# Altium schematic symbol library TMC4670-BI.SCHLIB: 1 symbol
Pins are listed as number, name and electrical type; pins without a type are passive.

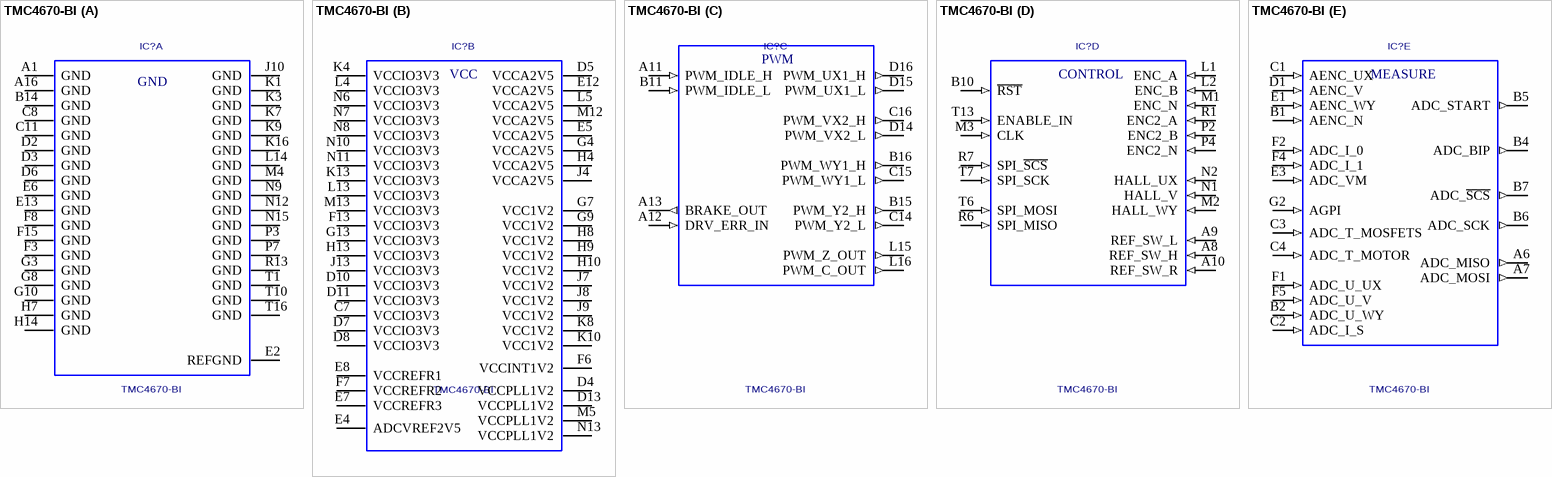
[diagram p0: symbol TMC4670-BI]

## TMC4670-BI
designator IC?
Field oriented servocontrolerfor torque control,velocity control,and positioning. Encoder Engine, PWM-Engine und SPI. BGA256(17x17); Manufacturer: TRINAMIC; Geometry.Height: 2.2mm; PCB DECAL: TMC_BGA256_1.0_17X17
footprint TMC_BGA256_1.0_17X17
part A pins: A1 GND (power), A16 GND (power), B14 GND (power), C8 GND (power), C11 GND (power), D2 GND (power), D3 GND (power), D6 GND (power), E2 REFGND (power), E6 GND (power), E13 GND (power), F3 GND (power), F8 GND (power), F15 GND (power), G3 GND (power), G8 GND (power), G10 GND (power), H7 GND (power), H14 GND (power), J10 GND (power), K1 GND (power), K3 GND (power), K7 GND (power), K9 GND (power), K16 GND (power), L14 GND (power), M4 GND (power), N9 GND (power), N12 GND (power), N15 GND (power), P3 GND (power), P7 GND (power), R13 GND (power), T1 GND (power), T10 GND (power), T16 GND (power)
part B pins: C7 VCCIO3V3 (power), D4 VCCPLL1V2 (power), D5 VCCA2V5 (power), D7 VCCIO3V3 (power), D8 VCCIO3V3 (power), D10 VCCIO3V3 (power), D11 VCCIO3V3 (power), D13 VCCPLL1V2 (power), E4 ADCVREF2V5 (power), E5 VCCA2V5 (power), E7 VCCREFR3 (power), E8 VCCREFR1 (power), E12 VCCA2V5 (power), F6 VCCINT1V2 (power), F7 VCCREFR2 (power), F13 VCCIO3V3 (power), G4 VCCA2V5 (power), G7 VCC1V2 (power), G9 VCC1V2 (power), G13 VCCIO3V3 (power), H4 VCCA2V5 (power), H8 VCC1V2 (power), H9 VCC1V2 (power), H10 VCC1V2 (power), H13 VCCIO3V3 (power), J4 VCCA2V5 (power), J7 VCC1V2 (power), J8 VCC1V2 (power), J9 VCC1V2 (power), J13 VCCIO3V3 (power), K4 VCCIO3V3 (power), K8 VCC1V2 (power), K10 VCC1V2 (power), K13 VCCIO3V3 (power), L4 VCCIO3V3 (power), L5 VCCA2V5 (power), L13 VCCIO3V3 (power), M5 VCCPLL1V2 (power), M12 VCCA2V5 (power), M13 VCCIO3V3 (power), N6 VCCIO3V3 (power), N7 VCCIO3V3 (power), N8 VCCIO3V3 (power), N10 VCCIO3V3 (power), N11 VCCIO3V3 (power), N13 VCCPLL1V2 (power)
part C pins: A11 PWM_IDLE_H (in), A12 DRV_ERR_IN (in), A13 BRAKE_OUT (out), B11 PWM_IDLE_L (in), B15 PWM_Y2_H (out), B16 PWM_WY1_H (out), C14 PWM_Y2_L (out), C15 PWM_WY1_L (out), C16 PWM_VX2_H (out), D14 PWM_VX2_L (out), D15 PWM_UX1_L (out), D16 PWM_UX1_H (out), L15 PWM_Z_OUT (out), L16 PWM_C_OUT (out)
part D pins: A8 REF_SW_H (in), A9 REF_SW_L (in), A10 REF_SW_R (in), B10 ~{RST} (in), L1 ENC_A (in), L2 ENC_B (in), M1 ENC_N (in), M2 HALL_WY (in), M3 CLK (in), N1 HALL_V (in), N2 HALL_UX (in), P2 ENC2_B (in), P4 ENC2_N (in), R1 ENC2_A (in), R6 SPI_MISO (in), R7 SPI_~{SCS} (in), T6 SPI_MOSI (in), T7 SPI_SCK (in), T13 ENABLE_IN (in)
part E pins: A6 ADC_MISO (out), A7 ADC_MOSI (out), B1 AENC_N (in), B2 ADC_U_WY (in), B4 ADC_BIP (out), B5 ADC_START (out), B6 ADC_SCK (out), B7 ADC_~{SCS} (out), C1 AENC_UX (in), C2 ADC_I_S (in), C3 ADC_T_MOSFETS (in), C4 ADC_T_MOTOR (in), D1 AENC_V (in), E1 AENC_WY (in), E3 ADC_VM (in), F1 ADC_U_UX (in), F2 ADC_I_0 (in), F4 ADC_I_1 (in), F5 ADC_U_V (in), G2 AGPI (in)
